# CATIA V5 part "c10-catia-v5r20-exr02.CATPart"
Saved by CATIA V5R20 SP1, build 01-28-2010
Part number: Part1
Bounding box of the stored display mesh (mm): x -45.49 to 45.49, y -82.99 to 82.99, z -2.5 to 26.498
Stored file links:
  D:\v5_r20\psrt_files_downloaded\c10\c10-catia-v5r20-exr02.CATPart
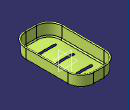
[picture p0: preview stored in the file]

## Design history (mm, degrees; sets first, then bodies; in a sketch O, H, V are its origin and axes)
Set1
  Sketch1 on xy-plane, origin (0, 0, 0), H (1, 0, 0), V (0, 1, 0)
    line L1 (37.5, 50) -> (37.5, -50)
    line L2 (12.5, -75) -> (-12.5, -75)
    line L3 (-37.5, -50) -> (-37.5, 50)
    line L4 (-12.5, 75) -> (12.5, 75)
    arc A1 centre (12.5, 50) radius 25 from (37.5, 50) to (12.5, 75) ccw
    arc A2 centre (-12.5, 50) radius 25 from (-37.5, 50) to (-12.5, 75) cw
    arc A3 centre (-12.5, -50) radius 25 from (-12.5, -75) to (-37.5, -50) cw
    arc A4 centre (12.5, -50) radius 25 from (37.5, -50) to (12.5, -75) cw
    radius A1 = 25
    radius A2 = 25
    radius A3 = 25
    radius A4 = 25
    length L1 = 100
    length L4 = 25
    vertical: L1 V, L3 V
    horizontal: L2 H, L4 H
    equidistance: L1 L3 O, L2 L4 O
    tangency: A1 L1, A1 L4, A2 L3, A2 L4, A3 L2, A3 L3, A4 L1, A4 L2
  Sketch2 on yz-plane, origin (0, 0, 0), H (0, 1, 0), V (0, 0, 1)
    arc A1 centre (-77.5, 0) radius 2.5 from (-80, 0) to (-75, 0) ccw
    point P1 (-77.5, 0)
    point P2 (-75, 0)
    line L1 (-80, 0) -> (-80, 25)
    arc A2 centre (-81.5, 25) radius 1.5 from (-80, 25) to (-82.9905, 25.1687) ccw
    distance P1 V = 77.5
    radius A1 = 2.5
    length L1 = 25
    radius A2 = 1.5
    coincidence: P1 H, P2 H
    vertical: L1 V
    tangency: A2 L1, A1 L1
  Sweep1: type Unspec, Profile Sketch2, Guide Sketch1
  Fill1: Boundary (edge of Sweep1; edge of Sweep1; edge of Sweep1; edge of Sweep1; edge of Sweep1; edge of Sweep1; edge of Sweep1; edge of Sweep1), Constraint {point type Coord, X 0, Y 0, Z 5}
  Sketch3 on xy-plane, origin (0, 0, 0), H (1, 0, 0), V (0, 1, 0)
    construction line L1 (-20, 42.5) -> (20, 42.5)
    point P2 (20, 42.5)
    line L2 (-20, 45) -> (20, 45)
    line L3 (20, 40) -> (-20, 40)
    arc A1 centre (20, 42.5) radius 2.5 from (20, 45) to (20, 40) cw
    arc A2 centre (-20, 42.5) radius 2.5 from (-20, 40) to (-20, 45) cw
    construction line L4 (-20, 0) -> (20, 0)
    point P7 (-20, 0)
    point P8 (20, 0)
    line L5 (-20, 2.5) -> (20, 2.5)
    line L6 (20, -2.5) -> (-20, -2.5)
    arc A3 centre (20, 0) radius 2.5 from (20, 2.5) to (20, -2.5) cw
    arc A4 centre (-20, 0) radius 2.5 from (-20, -2.5) to (-20, 2.5) cw
    construction line L7 (-20, -42.5) -> (20, -42.5)
    point P14 (20, -42.5)
    line L8 (-20, -40) -> (20, -40)
    line L9 (20, -45) -> (-20, -45)
    arc A5 centre (20, -42.5) radius 2.5 from (20, -40) to (20, -45) cw
    arc A6 centre (-20, -42.5) radius 2.5 from (-20, -45) to (-20, -40) cw
    length L2 = 40
    distance L2 L3 = 5
    distance L3 H = 40
    distance P2 V = 20
    length L6 = 40
    distance L5 L6 = 5
    distance P8 V = 20
    length L9 = 40
    distance L8 L9 = 5
    distance P14 V = 20
    distance L8 L4 = 40
    horizontal: L1 H, L4 H, L7 H
    tangency: A1 L2, A2 L2, A1 L3, A2 L3, A3 L5, A4 L5, A3 L6, A4 L6, A5 L8, A6 L8, A5 L9, A6 L9
    parallelism: L1 L2, L4 L5, L7 L8
    coincidence: P7 H
  Extrude1: Element1 Sketch3, Lim1 5, Lim2 5, Direction xy-plane
  Split1: ToCut Fill1, Cutting Extrude1
Body1 (main body)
